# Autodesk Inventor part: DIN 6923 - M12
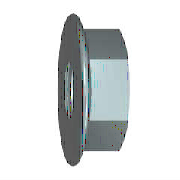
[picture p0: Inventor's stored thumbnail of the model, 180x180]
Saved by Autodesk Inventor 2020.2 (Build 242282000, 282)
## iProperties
Manager: www.cadconsulting.pl
Company: Fabian Stasiak CAD Consulting
Created: 2010-02
Part Number: DIN 6923 - M12
Material: Stal, miękka
Description: Nakrętka
Document SubType Name: Modeling
Standard: DIN 6923
Designer: F.Stasiak
Standards Organization: DIN
Language: pl-PL
Size Designation: M12
Categories: <MemberInstance><Categories><Category DisplayName="Mocowania" InternalName="e4da775c-781d-43d5-af7c-5136215cf5a6" Mnemonic="FSTN"><Category DisplayName="Nakrętk
Density: 1 g/cm^3
Appearance: Stal
IsCustomPart: 0
Author: F.Stasiak
Subject: Zbiór ćwiczeń. Autodesk Inventor 2020. Kurs podstawowy
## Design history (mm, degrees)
sketch "Sketch1"
  geometry: L1 (-2.766, 0)-(14.461, 0) reference; L2 (4.812, 9)-(3.431, 11.961); L3 (4.812, 9)-(12, 9); L4 (12, 9)-(12, 0); L5 (4.812, 9)-(4.812, 0); L6 (0, -2.668)-(0, 16.005) reference; A1 r 1.8 centre (1.8, 11.2) between (3.431, 11.961) and (0, 11.2); 1 further point
  constraints: 8 end point, 3 point on line, 2 perpendicular, 2 point on circle, 2 tangent, 1 centre point, 1 parallel
  dimensions: "d2" = 18 diameter of L3 L1 (= SW); "d4" = 26 dimension on A1 L1 (= LADI); "d5" = 1.8 radius of A1 (= PHH); "d15" = 12 distance between parallel lines of L4 L6 (= KOH); "d16" = 25 deg angle of L6 L2 (= KEWI)
revolve "Ring" sketch "Sketch1" stored, may be unused: angle "d8" = 90 deg
sketch "Sketch2"
  geometry: L1 (-9, -5.196)-(-9, 5.196); L2 (-9, 5.196)-(0, 10.392); L3 (0, 10.392)-(9, 5.196); L4 (9, 5.196)-(9, -5.196); L5 (9, -5.196)-(0, -10.392); L6 (0, -10.392)-(-9, -5.196); C1 r 4.9 at (0, 0); C2 r 11.2 at (0, 0) reference; 1 further point
  constraints: 12 end point, 1 centre point, 1 coincident, 1 vertical, 11 other
  dimensions: "d6" = 20.78461 distance of L5.end L2.end (= 1.1547 x SW)
extrude "Body" join sketch "Sketch2" distance "d7" = 12 (= KOH); taper "d9" = 0 deg
sketch "Sketch3"
  geometry: L1 (4.163, 10.392)-(12, 10.392) reference; L2 (12, 5.196)-(12, 10.392) reference; L3 (0, -11.2)-(0, 11.2) reference; L4 (-2.4, 0)-(14.4, 0) reference; L5 (11.627, 10.392)-(12, 9)
  constraints: 2 end point, 2 point on line
  dimensions: "d10" = 15 deg angle of L2 L5 (= ANG1); "d11" = 18 diameter of L5.end L4 (= SW0)
revolve "Chamfer1" sketch "Sketch3" stored, may be unused: angle "d24" = 90 deg
sketch "Sketch4"
  geometry: C1 r 11.2 at (0, 0) reference; 1 further point
  constraints: 1 coincident
hole "Thread" sketch "Sketch4" at (0, 0) diameter "d25" = 10.106; stored, may be unused: countersink angle "d29" = 82 deg, drill point angle "d31" = 118 deg; dims "d26" = 6, "d27" = 4, "d28" = 2, "d30" = 8
chamfer "Chamfer2" distance "d12" = 0.94722 (= -0.5 x GD1 + 0.5 x NND); stored, may be unused: angle "d13" = 30 deg, second distance "d46" = 0.94722 (= -0.5 x GD1 + 0.5 x NND)
workaxis "Work Axis1"
workplane "Work Plane1"
chamfer "Chamfer3" distance "d51" = 0.94722 (= -0.5 x GD1 + 0.5 x NND); stored, may be unused: second distance "d52" = 2, angle "d53" = 45 deg
body "Solid1"
other parameters: "ANG1" = 15 deg [user parameter; used in 1 equation term], "KEWI" = 25 deg [user parameter; used in 1 equation term], "NND" = 12 [user parameter; used in 4 equation terms], "LADI" = 26 [user parameter; used in 2 equation terms], "SW" = 18 [user parameter; used in 4 equation terms], "PHH" = 1.8 (= RR) [user parameter; used in 2 equation terms], "KOH" = 12 (= NND) [user parameter; used in 2 equation terms], "SW0" = 18 (= SW) [user parameter; used in 1 equation term], "GD1" = 10.10557 (computed from THREADDIA, PTC, TOA) [user parameter; used in 3 equation terms], "d1" = 26 (= LADI), "d3" = 1.8 (= PHH), "d45" = 0, "d47" = 0, "d49" = 0, "d54" = 0, "GUL" = 0.94722 (= 0.541266 x PTC) [user parameter], "TPU" = 5.71429 (computed from PTC) [user parameter], "RR" = 1.8 [user parameter; used in 1 equation term], "THREADDIA" = 12 [user parameter; used in 1 equation term], "TOA" = 30 deg [user parameter; used in 1 equation term], "PTC" = 1.75 [user parameter; used in 4 equation terms], "GAL" = 0.94722 (= 0.541266 x PTC) [user parameter], "E0" = 20.79 (= 1.155 x SW) [user parameter]
